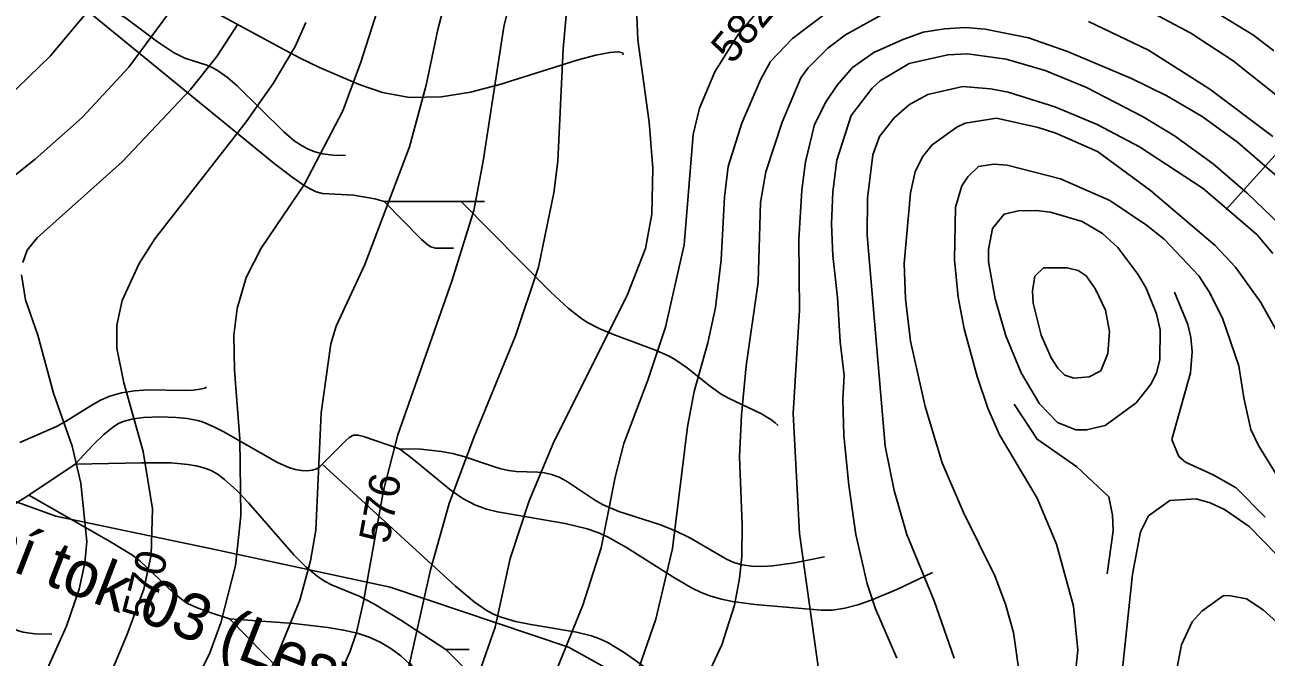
# Model space of a CAD drawing. Extents: x -709584 to -702006, y -1161789 to -1157496.
# Drawn here: x -708453.2 to -708051.5, y -1159134.4 to -1158929.8 of the extents above; entities that cross this region are included whole.
import ezdxf

# ---------------------------------------------------------------- set-up
doc = ezdxf.new("R2010")
doc.units = 0
for name, color, linetype in [('120_vrstevnice hlavní', 7, 'Continuous'), ('121_vrstevnice hlavní_popis', 7, 'Continuous'), ('122_vrstevnice základní', 7, 'Continuous'), ('124_vrstevnice doplňková', 7, 'Continuous'), ('411_akumulovaný odtok', 7, 'Continuous'), ('501_vodní tok', 7, 'Continuous'), ('502_vodní tok_popis', 7, 'Continuous')]:
    doc.layers.add(name, color=color, linetype=linetype)

msp = doc.modelspace()

# ---------------------------------------------------------------- linework, layer by layer
at = {"layer": '120_vrstevnice hlavní'}
for points in [[(-708255.34, -1158921.44), (-708254.8, -1158934.62), (-708251.19, -1158961.3), (-708250.05, -1158976.16), (-708250.34, -1158991.01), (-708252.34, -1159002.16), (-708258.19, -1159017.02), (-708282.2, -1159065.3), (-708290.05, -1159083.88), (-708296.2, -1159102.45), (-708301.05, -1159124.74), (-708307.77, -1159144.17), (-708318.2, -1159164.17), (-708340.91, -1159202.17), (-708348.63, -1159218.17), (-708355.2, -1159234.17), (-708357.77, -1159241.6), (-708368.2, -1159278.74), (-708374.49, -1159297.31), (-708382.49, -1159315.89), (-708396.06, -1159340.91), (-708404.2, -1159356.59), (-708412.94, -1159374.47)], [(-708459.92, -1159197.88), (-708451.2, -1159183.02), (-708436.92, -1159160.74), (-708426.49, -1159142.17), (-708420.2, -1159127.31), (-708414.77, -1159112.45), (-708412.34, -1159101.31), (-708411.92, -1159086.45), (-708414.92, -1159067.88), (-708421.2, -1159045.59), (-708423.49, -1159034.45), (-708423.49, -1159027.02), (-708421.77, -1159019.02), (-708416.2, -1159007.02), (-708411.2, -1158999.02), (-708381.63, -1158961.16), (-708372.91, -1158948.73), (-708365.77, -1158936.73), (-708362.34, -1158929.01)], [(-708028.33, -1159012.44), (-708057.61, -1158984.3), (-708068.61, -1158974.73), (-708081.19, -1158965.73), (-708091.33, -1158959.58), (-708109.62, -1158950.01), (-708123.05, -1158944.58), (-708135.62, -1158940.87), (-708148.19, -1158939.16), (-708154.48, -1158939.44), (-708167.05, -1158942.3), (-708176.48, -1158947.87), (-708179.05, -1158950.3), (-708185.76, -1158959.16), (-708190.48, -1158973.58), (-708191.76, -1158983.87), (-708192.19, -1158994.16), (-708191.76, -1159004.44), (-708190.19, -1159018.02), (-708189.42, -1159032.35), (-708188.05, -1159043.3), (-708188.48, -1159051.02), (-708188.19, -1159062.73), (-708186.62, -1159078.73), (-708184.33, -1159094.73), (-708180.62, -1159110.74), (-708177.91, -1159118.74), (-708171.05, -1159134.74)], [(-708108.76, -1159043.73), (-708105.04, -1159041.73), (-708102.76, -1159036.16), (-708102.19, -1159029.02), (-708103.47, -1159022.16), (-708106.76, -1159015.3), (-708109.76, -1159011.02), (-708112.33, -1159009.3), (-708115.9, -1159008.44), (-708123.52, -1159008.37), (-708126.32, -1159011.15), (-708127.09, -1159015.9), (-708126.9, -1159019.87), (-708124.33, -1159030.16), (-708121.05, -1159037.59), (-708118.9, -1159040.87), (-708116.62, -1159043.16), (-708113.76, -1159044.16), (-708108.76, -1159043.73)], [(-708084.33, -1159158.45), (-708078.9, -1159130.45), (-708075.47, -1159123.02), (-708072.33, -1159119.59), (-708065.47, -1159114.59), (-708063.61, -1159114.45), (-708057.9, -1159115.59), (-708052.47, -1159119.16), (-708045.9, -1159125.02)]]:
    msp.add_lwpolyline(points, dxfattribs=at)
at = {"layer": '122_vrstevnice základní'}
for points in [[(-708335.91, -1158914.73), (-708344.48, -1158941.87), (-708350.34, -1158957.58), (-708362.77, -1158981.3), (-708376.77, -1159002.02), (-708381.63, -1159011.59), (-708384.49, -1159021.59), (-708385.63, -1159030.16), (-708385.34, -1159041.59), (-708383.63, -1159063.88), (-708383.34, -1159088.73), (-708385.06, -1159104.73), (-708389.77, -1159123.31), (-708393.34, -1159133.02), (-708399.06, -1159144.74), (-708416.49, -1159171.17), (-708441.35, -1159214.6), (-708454.63, -1159242.03), (-708473.21, -1159283.31), (-708481.35, -1159299.74), (-708491.2, -1159322.74), (-708494.33, -1159331.82), (-708497.58, -1159346.85), (-708500.21, -1159363.79)], [(-708467.47, -1159367.8), (-708465.02, -1159351.65), (-708462.35, -1159339.89), (-708453.28, -1159311.24), (-708445.63, -1159295.89), (-708431.34, -1159263.03), (-708425.92, -1159247.6), (-708423.77, -1159239.03), (-708415.77, -1159218.45), (-708399.49, -1159185.88), (-708383.56, -1159157.17), (-708372.34, -1159135.74), (-708364.2, -1159116.02), (-708360.77, -1159103.31), (-708359.06, -1159093.3), (-708357.34, -1159055.3), (-708354.2, -1159033.02), (-708352.48, -1159027.3), (-708343.2, -1159007.3), (-708328.77, -1158969.3), (-708323.34, -1158949.3), (-708319.63, -1158931.3), (-708315.91, -1158917.3)], [(-708294.91, -1158916.73), (-708298.2, -1158930.44), (-708304.91, -1158973.87), (-708307.91, -1158989.87), (-708315.05, -1159012.73), (-708332.48, -1159062.45), (-708337.2, -1159080.45), (-708343.63, -1159116.45), (-708345.91, -1159126.45), (-708347.91, -1159132.45), (-708353.2, -1159144.45), (-708365.34, -1159168.45), (-708382.34, -1159199.02), (-708385.2, -1159205.88), (-708400.77, -1159251.6), (-708417.63, -1159304.17), (-708431.22, -1159340.61), (-708436.04, -1159354.92), (-708440.9, -1159371.05)], [(-708079.04, -1158918.73), (-708055.61, -1158933.15), (-708049.04, -1158938.15)], [(-708094.76, -1158922.44), (-708075.9, -1158932.44), (-708062.19, -1158941.44), (-708041.61, -1158957.87)], [(-708469.49, -1158963.58), (-708445.06, -1158939.87), (-708432.2, -1158924.58)], [(-708406.77, -1158926.15), (-708419.63, -1158943.44), (-708434.63, -1158959.73), (-708449.92, -1158973.3), (-708462.2, -1158983.01)], [(-708425.49, -1159372.93), (-708403.34, -1159326.75), (-708396.63, -1159310.74), (-708389.92, -1159291.6), (-708378.63, -1159253.88), (-708373.77, -1159240.17), (-708359.34, -1159207.6), (-708339.48, -1159168.74), (-708333.63, -1159153.31), (-708328.91, -1159137.59), (-708321.91, -1159106.16), (-708315.91, -1159084.73), (-708307.91, -1159063.3), (-708294.48, -1159030.45), (-708287.05, -1159008.16), (-708282.05, -1158984.16), (-708280.77, -1158973.87), (-708279.05, -1158937.58), (-708277.91, -1158925.58)], [(-708283.05, -1159143.16), (-708272.62, -1159117.59), (-708266.77, -1159099.02), (-708262.19, -1159076.16), (-708259.34, -1159065.3), (-708251.62, -1159044.73), (-708245.91, -1159027.59), (-708239.91, -1159001.02), (-708236.91, -1158965.3), (-708234.91, -1158956.73), (-708229.91, -1158945.01), (-708222.33, -1158932.87), (-708215.76, -1158925.15)], [(-708255.62, -1159141.16), (-708249.05, -1159122.16), (-708243.62, -1159099.3), (-708238.77, -1159059.88), (-708236.62, -1159048.45), (-708232.19, -1159032.73), (-708229.76, -1159021.3), (-708227.91, -1159005.87), (-708226.76, -1158985.59), (-708225.62, -1158975.58), (-708221.19, -1158961.58), (-708215.19, -1158947.58), (-708211.91, -1158941.58), (-708204.76, -1158934.15), (-708193.76, -1158925.87)], [(-708174.76, -1158925.87), (-708187.62, -1158933.01), (-708193.33, -1158937.3), (-708199.76, -1158943.73), (-708202.05, -1158946.87), (-708208.19, -1158961.3), (-708213.48, -1158977.3), (-708215.19, -1158987.3), (-708215.91, -1159013.02), (-708219.76, -1159040.16), (-708221.33, -1159056.16), (-708221.91, -1159069.59), (-708221.05, -1159091.59), (-708221.19, -1159101.88), (-708221.91, -1159109.02), (-708223.62, -1159117.59), (-708227.62, -1159130.45), (-708235.05, -1159146.17)], [(-708453.92, -1159006.73), (-708452.49, -1159002.73), (-708449.2, -1158998.73), (-708421.77, -1158974.16), (-708399.63, -1158950.73), (-708391.06, -1158940.01), (-708384.34, -1158929.58)], [(-708196.19, -1159139.88), (-708202.48, -1159094.45), (-708204.62, -1159055.59), (-708202.48, -1159022.16), (-708202.76, -1158999.3), (-708201.76, -1158983.3), (-708200.62, -1158974.16), (-708197.73, -1158962), (-708193.91, -1158954.58), (-708190.33, -1158949.3), (-708185.33, -1158943.58), (-708178.48, -1158938.73), (-708169.33, -1158934.58), (-708162.48, -1158932.15), (-708155.62, -1158931.01), (-708148.76, -1158930.58), (-708142.48, -1158931.15), (-708128.47, -1158934.01), (-708115.76, -1158938.44), (-708095.04, -1158947.16), (-708083.62, -1158952.73), (-708072.19, -1158959.44), (-708060.76, -1158967.73), (-708046.33, -1158980.3)], [(-708049.33, -1158965.87), (-708069.76, -1158950.58), (-708089.62, -1158938.01), (-708109.04, -1158928.73)], [(-708152.48, -1159134.74), (-708158.9, -1159116.16), (-708167.76, -1159094.73), (-708171.9, -1159080.45), (-708174.76, -1159066.16), (-708180.62, -1158997.87), (-708180.48, -1158985.87), (-708178.76, -1158971.87), (-708176.62, -1158965.87), (-708171.9, -1158959.87), (-708166.9, -1158955.58), (-708161.05, -1158952.3), (-708149.62, -1158949.73), (-708140.76, -1158950.44), (-708135.05, -1158951.58), (-708119.9, -1158956.3), (-708106.19, -1158962.01), (-708092.47, -1158969.3), (-708071.9, -1158982.73), (-708054.47, -1158997.73), (-708049.33, -1159003.73)], [(-708048.47, -1159028.16), (-708053.18, -1159019.59), (-708061.47, -1159008.16), (-708068.04, -1159001.16), (-708088.9, -1158983.44), (-708106.11, -1158970.72), (-708119.62, -1158964.87), (-708125.33, -1158963.01), (-708138.76, -1158960.01), (-708148.97, -1158961.61), (-708151.62, -1158962.87), (-708159.62, -1158968.58), (-708162.76, -1158972.44), (-708165.05, -1158977.3), (-708166.62, -1158984.16), (-708168.62, -1159007.02), (-708168.19, -1159018.44), (-708166.62, -1159032.16), (-708161.9, -1159053.3), (-708156.33, -1159071.59), (-708149.48, -1159087.59), (-708139.33, -1159108.16), (-708135.9, -1159117.31), (-708133.33, -1159126.45), (-708131.33, -1159140.17)], [(-708042.47, -1159084.73), (-708054.04, -1159065.88), (-708056.47, -1159060.73), (-708058.76, -1159050.45), (-708060.33, -1159040.16), (-708065.61, -1159024.73), (-708069.9, -1159016.16), (-708073.33, -1159011.02), (-708084.47, -1158999.16), (-708090.19, -1158994.59), (-708102.06, -1158986.6), (-708118.05, -1158979.58), (-708135.33, -1158975.16), (-708139.62, -1158974.87), (-708144.62, -1158975.58), (-708148.05, -1158979.01), (-708150.05, -1158981.87), (-708152.05, -1158988.73), (-708152.33, -1159005.87), (-708151.19, -1159017.87), (-708149.19, -1159028.16), (-708145.05, -1159043.59), (-708141.62, -1159053.88), (-708137.76, -1159062.45), (-708125.62, -1159083.02), (-708119.33, -1159097.88), (-708113.9, -1159117.88), (-708112.47, -1159132.16), (-708113.62, -1159143.59)], [(-708085.76, -1159028.45), (-708087.04, -1159023.3), (-708090.37, -1159015), (-708093.04, -1159010.44), (-708099.47, -1159001.87), (-708104.47, -1158997.3), (-708111.05, -1158993.44), (-708121.33, -1158990.44), (-708125.9, -1158989.87), (-708131.62, -1158990.01), (-708136.33, -1158991.01), (-708140.05, -1158995.73), (-708141.33, -1159002.44), (-708141.33, -1159006.44), (-708139.19, -1159018.44), (-708135.76, -1159030.45), (-708130.76, -1159042.45), (-708124.9, -1159052.45), (-708119.05, -1159058.45), (-708113.05, -1159060.88), (-708109.62, -1159060.88), (-708103.62, -1159059.45), (-708093.62, -1159052.16), (-708088.76, -1159046.02), (-708087.04, -1159042.45), (-708085.9, -1159038.16), (-708085.76, -1159028.45)], [(-708459.92, -1159164.74), (-708449.78, -1159146.74), (-708439.77, -1159124.45), (-708435.63, -1159112.45), (-708433.77, -1159103.88), (-708433.2, -1159097.02), (-708435.06, -1159078.16), (-708437.92, -1159066.16), (-708443.92, -1159049.02), (-708449.06, -1159030.16), (-708453.06, -1159018.73), (-708454.35, -1159010.73)], [(-708098.76, -1159145.31), (-708094.76, -1159107.59), (-708092.19, -1159093.88), (-708089.62, -1159088.73), (-708082.69, -1159083.7), (-708074.19, -1159083.16), (-708069.61, -1159084.45), (-708065.04, -1159086.59), (-708057.04, -1159092.16), (-708048.04, -1159101.31)]]:
    msp.add_lwpolyline(points, dxfattribs=at)
at = {"layer": '124_vrstevnice doplňková'}
for points in [[(-708051.83, -1159089.07), (-708061.25, -1159079.58), (-708068.71, -1159075.41), (-708077.61, -1159071.3), (-708079.76, -1159069.45), (-708082.04, -1159064.02), (-708076.04, -1159042.45), (-708075.47, -1159035.59), (-708075.9, -1159031.02), (-708076.9, -1159026.73), (-708081.19, -1159016.3)], [(-708102.92, -1159107.46), (-708101.04, -1159093.59), (-708101.19, -1159088.45), (-708102.47, -1159082.59), (-708112.76, -1159072.88), (-708125.62, -1159063.88), (-708133.05, -1159052.59)]]:
    msp.add_lwpolyline(points, dxfattribs=at)
at = {"layer": '411_akumulovaný odtok'}
for p, q in [((-708311.99, -1158987), (-708336.99, -1158987)), ((-708304.49, -1158987), (-708311.99, -1158987)), ((-708436.99, -1159072), (-708451.99, -1159082)), ((-708309.49, -1159132), (-708316.99, -1159132))]:
    msp.add_line(p, q, dxfattribs=at)
for points in [[(-708064.49, -1158989.5), (-708032.12, -1158953.66), (-708021.15, -1158941.89), (-708016.6, -1158937.34), (-708012.09, -1158933.16), (-707993.72, -1158916.95), (-707989.5, -1158912.76), (-707987.56, -1158910.58), (-707985.81, -1158908.31), (-707984.31, -1158905.92), (-707983.13, -1158903.46), (-707979.37, -1158893.04), (-707977.94, -1158890.15), (-707970.57, -1158877.46), (-707969.04, -1158874.49), (-707967.91, -1158871.82), (-707967.3, -1158869.93), (-707966.97, -1158868.42), (-707966.87, -1158867.42), (-707966.99, -1158867)], [(-708349.49, -1158972), (-708352.62, -1158972.03), (-708356.94, -1158971.48), (-708359.34, -1158970.84), (-708361.76, -1158969.88), (-708364.05, -1158968.65), (-708366.12, -1158967.27), (-708369.44, -1158964.4), (-708384.49, -1158949.54), (-708387.61, -1158946.84), (-708390.89, -1158944.5), (-708392.62, -1158943.56), (-708394.34, -1158942.86), (-708401.47, -1158940.55), (-708405.09, -1158938.73), (-708410.28, -1158935.26), (-708420.68, -1158927.45), (-708425.28, -1158924.81), (-708427.72, -1158923.71), (-708430.12, -1158922.87), (-708432.25, -1158922.36), (-708435.61, -1158921.95), (-708436.99, -1158922)], [(-708336.99, -1158987), (-708340, -1158986.1), (-708346.85, -1158984.92), (-708356.87, -1158984.37), (-708358.99, -1158983.78), (-708360.93, -1158982.89), (-708362.88, -1158981.76), (-708366.77, -1158979.06), (-708372.61, -1158974.49), (-708436.99, -1158922)], [(-708259.49, -1158939.5), (-708259.83, -1158938.8), (-708261.06, -1158938.49), (-708263.95, -1158938.69), (-708268.42, -1158939.57), (-708274.12, -1158941.05), (-708299.55, -1158949.1), (-708308.97, -1158951.55), (-708318.34, -1158953.11), (-708328.71, -1158953.26), (-708337.45, -1158951.7), (-708344.99, -1158949.04), (-708357.84, -1158943.58), (-708364.15, -1158940.51), (-708370.55, -1158937.13), (-708400.94, -1158920.57)], [(-708314.49, -1159002), (-708320.38, -1159002), (-708321.83, -1159001.63), (-708322.75, -1159001.09), (-708324.84, -1158999.21), (-708336.99, -1158987)], [(-708209.49, -1159059.5), (-708210.38, -1159058.58), (-708211.49, -1159057.74), (-708214.78, -1159055.68), (-708225.49, -1159050.64), (-708227.85, -1159049.27), (-708231.74, -1159046.49), (-708238.89, -1159040.74), (-708242.68, -1159038.16), (-708244.76, -1159037.03), (-708249.12, -1159035.06), (-708262.7, -1159030), (-708267.13, -1159028.16), (-708271.34, -1159025.96), (-708273.43, -1159024.58), (-708277.38, -1159021.45), (-708283, -1159016.26), (-708311.99, -1158987)], [(-708394.49, -1159047), (-708395.03, -1159047.36), (-708396.51, -1159047.71), (-708398.75, -1159048), (-708401.61, -1159048.15), (-708413.34, -1159047.96), (-708417.76, -1159048.24), (-708421.99, -1159048.88), (-708425.78, -1159049.91), (-708428.77, -1159051.26), (-708431.6, -1159052.88), (-708440.02, -1159058.17), (-708442.94, -1159059.75), (-708454.84, -1159064.93)], [(-708356.99, -1159072), (-708357.84, -1159072.9), (-708358.86, -1159073.49), (-708360.2, -1159073.96), (-708361.87, -1159074.17), (-708363.74, -1159074.07), (-708365.74, -1159073.68), (-708367.76, -1159073.08), (-708371.5, -1159071.47), (-708389.01, -1159061.42), (-708392.25, -1159059.76), (-708395.56, -1159058.35), (-708397.25, -1159057.81), (-708400.67, -1159057.15), (-708404.17, -1159056.83), (-708409.5, -1159056.7), (-708414.79, -1159056.87), (-708418.22, -1159057.26), (-708421.45, -1159058.12), (-708422.94, -1159058.82), (-708424.39, -1159059.73), (-708427.64, -1159062.39), (-708430.99, -1159065.65), (-708436.99, -1159072)], [(-708331.99, -1159067), (-708343.68, -1159063.02), (-708345.31, -1159062.61), (-708346.85, -1159062.59), (-708348.23, -1159063.29), (-708349.51, -1159064.4), (-708356.99, -1159072)], [(-708194.49, -1159102), (-708204.19, -1159103.95), (-708211.13, -1159104.85), (-708214.68, -1159105.04), (-708218.07, -1159104.97), (-708221.16, -1159104.55), (-708223.81, -1159103.75), (-708226.18, -1159102.68), (-708237.83, -1159095.96), (-708242.66, -1159093.5), (-708247.84, -1159091.52), (-708261.05, -1159087.29), (-708266.04, -1159085.14), (-708268.55, -1159083.72), (-708277.99, -1159077.49), (-708280.36, -1159076.23), (-708282.81, -1159075.29), (-708285.01, -1159074.81), (-708287.28, -1159074.57), (-708294.26, -1159074.31), (-708296.6, -1159074.06), (-708299.23, -1159073.48), (-708301.85, -1159072.66), (-708311.14, -1159069.47), (-708314.83, -1159068.52), (-708318.4, -1159067.86), (-708325.07, -1159067.14), (-708331.99, -1159067)], [(-708159.49, -1159107), (-708170.98, -1159112.56), (-708179.34, -1159116), (-708183.68, -1159117.46), (-708187.9, -1159118.56), (-708191.85, -1159119.18), (-708195.5, -1159119.23), (-708217.01, -1159117.36), (-708224.22, -1159116.43), (-708227.75, -1159115.71), (-708231.19, -1159114.72), (-708234.38, -1159113.46), (-708237.48, -1159111.95), (-708243.54, -1159108.45), (-708258.47, -1159098.9), (-708264.63, -1159095.54), (-708267.81, -1159094.14), (-708271.27, -1159092.94), (-708278.42, -1159091.18), (-708300.27, -1159087.45), (-708303.83, -1159086.55), (-708307.64, -1159085.12), (-708311.53, -1159083.09), (-708315.25, -1159080.54), (-708327.87, -1159070.12), (-708331.99, -1159067)], [(-708316.99, -1159132), (-708331.5, -1159122.45), (-708340.26, -1159117.14), (-708345.07, -1159114.66), (-708354, -1159111.02), (-708356.06, -1159109.99), (-708358.24, -1159108.58), (-708362.31, -1159105.18), (-708366.14, -1159101.3), (-708380.89, -1159084.51), (-708384.66, -1159080.5), (-708388.61, -1159076.88), (-708390.71, -1159075.34), (-708392.93, -1159074.07), (-708395.32, -1159073.13), (-708397.83, -1159072.48), (-708400.44, -1159072.05), (-708405.86, -1159071.59), (-708415.35, -1159071.51), (-708436.99, -1159072)], [(-708246.99, -1159142), (-708254.07, -1159136.56), (-708259.32, -1159132.9), (-708264.82, -1159129.63), (-708267.44, -1159128.4), (-708269.87, -1159127.55), (-708274.68, -1159126.37), (-708289.53, -1159123.87), (-708294.4, -1159122.88), (-708299.09, -1159121.5), (-708301.32, -1159120.58), (-708303.56, -1159119.39), (-708307.81, -1159116.5), (-708313.87, -1159111.49), (-708356.99, -1159072)], [(-708451.99, -1159082), (-708466.4, -1159090.96), (-708471.17, -1159093.57), (-708473.22, -1159094.53), (-708477.32, -1159095.98), (-708479.5, -1159096.46), (-708481.72, -1159096.78), (-708486.25, -1159097.13), (-708490.83, -1159097.24), (-708497.72, -1159097.12), (-708502.29, -1159096.8), (-708506.79, -1159096.13), (-708513.19, -1159094.33), (-708525.78, -1159089.87), (-708530, -1159088.76), (-708532.13, -1159088.42), (-708536.58, -1159088.31), (-708549.2, -1159089.48), (-708554.76, -1159089.48), (-708557.19, -1159089.21), (-708559.22, -1159088.73), (-708560.76, -1159088.09), (-708561.71, -1159087.46), (-708561.99, -1159087)], [(-708386.99, -1159122), (-708393.61, -1159119.89), (-708397.16, -1159118.58), (-708400.34, -1159117.15), (-708401.61, -1159116.41), (-708405.11, -1159113.66), (-708413.82, -1159105.29), (-708416.07, -1159103.29), (-708418.44, -1159101.47), (-708426.02, -1159096.77), (-708451.99, -1159082)], [(-708444.49, -1159127), (-708449.96, -1159126.92), (-708453.73, -1159126.35), (-708455.58, -1159125.82), (-708457.31, -1159125.09), (-708458.84, -1159124.22), (-708466.12, -1159118.5), (-708467.4, -1159117.66), (-708470.29, -1159116.15), (-708476.43, -1159113.71), (-708485.9, -1159110.48), (-708492.23, -1159108.67), (-708495.37, -1159108.14), (-708498.52, -1159108.2), (-708500.1, -1159108.47), (-708503.23, -1159109.35), (-708508.1, -1159111.15), (-708521.99, -1159117)], [(-708224.49, -1159249.5), (-708276.38, -1159192.92), (-708316.65, -1159148.7), (-708325.46, -1159139.59), (-708331.6, -1159134.06), (-708334.84, -1159131.62), (-708338.26, -1159129.54), (-708341.83, -1159127.94), (-708345.63, -1159126.69), (-708350.1, -1159125.66), (-708355.19, -1159124.81), (-708366.14, -1159123.55), (-708386.99, -1159122)], [(-708365.01, -1159144.5), (-708386.99, -1159122)], [(-708256.99, -1159177), (-708260.48, -1159173.41), (-708263.12, -1159170.96), (-708265.95, -1159168.71), (-708267.34, -1159167.82), (-708268.7, -1159167.15), (-708271.4, -1159166.16), (-708279.86, -1159163.83), (-708284, -1159162.49), (-708286.58, -1159161.29), (-708289.01, -1159159.65), (-708291.28, -1159157.73), (-708294.55, -1159154.62), (-708316.99, -1159132)]]:
    msp.add_lwpolyline(points, dxfattribs=at)
at = {"layer": '501_vodní tok'}
msp.add_lwpolyline([(-708185.81, -1159173.32), (-708217.14, -1159164.55), (-708233.28, -1159155.57), (-708277.32, -1159131.2), (-708334.96, -1159111.76), (-708393.23, -1159099.23), (-708443.15, -1159088.8), (-708478.44, -1159076.03), (-708511.65, -1159062.24), (-708570.15, -1159043.37), (-708670.5, -1158995.39), (-708750.74, -1158954.75), (-708757.67, -1158951.28), (-708787.21, -1158933.49), (-708802.4, -1158926.32), (-708802.62, -1158926.21), (-708817.69, -1158916.84), (-708823.29, -1158912.63)], dxfattribs=at)

# ---------------------------------------------------------------- texts
at = {"layer": '121_vrstevnice hlavní_popis'}
for s, rotation, p in [('582', 49.9908, (-708224.33, -1158942.82)), ('576', 79.5448, (-708335.39, -1159098.05)), ('570', 75.7806, (-708412.28, -1159123.11))]:
    msp.add_text(s, height=10, rotation=rotation, dxfattribs=at).set_placement(p)
at = {"layer": '502_vodní tok_popis'}
msp.add_text('Bezejmenný vodní tok 03 (Lesy ČR, s.p.)', height=15, rotation=338.8028, dxfattribs=at).set_placement((-708606.47, -1159048.85))

doc.saveas('drawing.dxf')
